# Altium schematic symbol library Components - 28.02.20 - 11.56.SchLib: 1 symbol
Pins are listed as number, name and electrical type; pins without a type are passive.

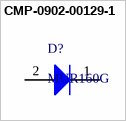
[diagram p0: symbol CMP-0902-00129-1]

## CMP-0902-00129-1
designator D?, comment MUR160G
SWITCHMODE(TM) Power Rectifier, 2-Pin Axial_Lead, Pb-Free, Bulk Bag; Manufacturer: On Semiconductor; IFSM Max (A): 35; VRRM Max (V): 600; Type: Ultrafast
footprint ONSC-AXIAL_LEAD-2-59-10_P (AXIAL, 2-Leads, Diameter 2.35mm)
pins: 1 K, 2 A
